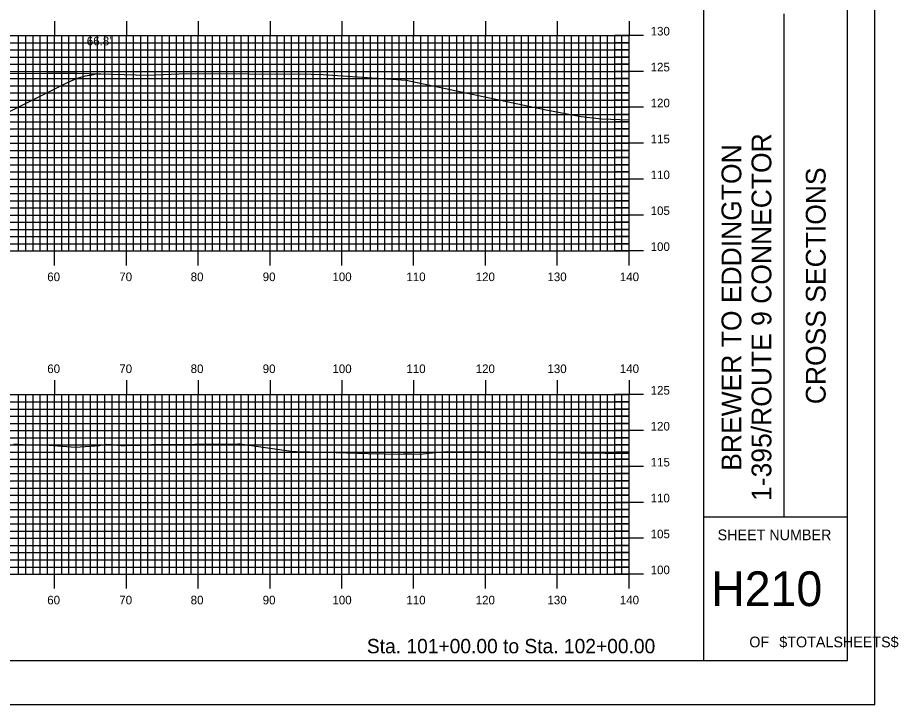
# Model space of a CAD drawing. Extents: x 1766907 to 1767250, y 442591 to 442811.
# Drawn here: x 1767127.3 to 1767249.9, y 442590.5 to 442686.2 of the extents above; entities that cross this region are included whole.
import ezdxf

# ---------------------------------------------------------------- set-up
doc = ezdxf.new("R2010")
doc.units = 0
for name, color, linetype in [('BORDER', 7, 'Continuous'), ('D_Roadway_Centerline', 7, 'Continuous'), ('D_Roadway_SlopeLines', 7, 'Continuous'), ('D_Text_Standard', 7, 'Continuous'), ('H_V ANNOTATION', 7, 'Continuous'), ('MAJOR', 7, 'Continuous'), ('MINOR', 7, 'Continuous'), ('PLOT BOUNDARY', 7, 'Continuous'), ('S_Roadway_Centerline', 7, 'Continuous')]:
    doc.layers.add(name, color=color, linetype=linetype)

msp = doc.modelspace()

# ---------------------------------------------------------------- linework, layer by layer
at = {"layer": 'BORDER'}
for p, q in [((1767222.82, 442596.67), (1767222.82, 442806.67)), ((1767234.01, 442616.67), (1767234.01, 442686.67)), ((1767222.82, 442616.67), (1767242.82, 442616.67))]:
    msp.add_line(p, q, dxfattribs=at)
msp.add_lwpolyline([(1766922.82, 442596.67), (1767242.82, 442596.67), (1767242.82, 442806.67), (1766922.82, 442806.67)], close=True, dxfattribs=at)
at = {"layer": 'D_Roadway_Centerline'}
msp.add_lwpolyline([(1767106.6, 442663.33), (1767134.22, 442677.14), (1767134.22, 442677.14), (1767135.34, 442677.63), (1767135.48, 442677.68), (1767135.6, 442677.72), (1767136.72, 442678.06), (1767137.89, 442678.26), (1767137.98, 442678.27), (1767138.05, 442678.28), (1767139.22, 442678.32)], dxfattribs=at)
at = {"layer": 'D_Roadway_SlopeLines'}
msp.add_lwpolyline([(1767106.6, 442663.33), (1767134.22, 442677.14), (1767135.48, 442677.68), (1767136.72, 442678.06), (1767137.98, 442678.27), (1767139.22, 442678.32)], dxfattribs=at)
at = {"layer": 'MAJOR'}
for p, q in [((1767132.42, 442685.67), (1767132.42, 442683.67)), ((1767142.42, 442685.67), (1767142.42, 442683.67)), ((1767152.42, 442685.67), (1767152.42, 442683.67)), ((1767162.42, 442685.67), (1767162.42, 442683.67)), ((1767172.42, 442685.67), (1767172.42, 442683.67)), ((1767182.42, 442685.67), (1767182.42, 442683.67)), ((1767192.42, 442685.67), (1767192.42, 442683.67)), ((1767202.42, 442685.67), (1767202.42, 442683.67)), ((1767212.42, 442685.67), (1767212.42, 442683.67)), ((1766932.42, 442683.67), (1767212.42, 442683.67)), ((1766932.42, 442683.67), (1767212.42, 442683.67)), ((1767132.42, 442653.67), (1767132.42, 442683.67)), ((1767142.42, 442653.67), (1767142.42, 442683.67)), ((1767152.42, 442653.67), (1767152.42, 442683.67)), ((1767162.42, 442653.67), (1767162.42, 442683.67)), ((1767172.42, 442653.67), (1767172.42, 442683.67)), ((1767182.42, 442653.67), (1767182.42, 442683.67)), ((1767192.42, 442653.67), (1767192.42, 442683.67)), ((1767202.42, 442653.67), (1767202.42, 442683.67)), ((1767214.43, 442683.67), (1767210.42, 442683.67)), ((1767212.42, 442653.67), (1767212.42, 442683.67)), ((1767212.42, 442653.67), (1767212.42, 442683.67)), ((1766932.42, 442678.67), (1767212.42, 442678.67)), ((1767214.43, 442678.67), (1767210.42, 442678.67)), ((1766932.42, 442673.67), (1767212.42, 442673.67)), ((1767214.43, 442673.67), (1767210.42, 442673.67)), ((1766932.42, 442668.67), (1767212.42, 442668.67)), ((1767214.43, 442668.67), (1767210.42, 442668.67)), ((1766932.42, 442663.67), (1767212.42, 442663.67)), ((1767214.43, 442663.67), (1767210.42, 442663.67)), ((1766932.42, 442658.67), (1767212.42, 442658.67)), ((1767214.43, 442658.67), (1767210.42, 442658.67)), ((1766932.42, 442653.67), (1767212.42, 442653.67)), ((1766932.42, 442653.67), (1767212.42, 442653.67)), ((1767132.42, 442651.66), (1767132.42, 442653.67)), ((1767142.42, 442651.66), (1767142.42, 442653.67)), ((1767152.42, 442651.66), (1767152.42, 442653.67)), ((1767162.42, 442651.66), (1767162.42, 442653.67)), ((1767172.42, 442651.66), (1767172.42, 442653.67)), ((1767182.42, 442651.66), (1767182.42, 442653.67)), ((1767192.42, 442651.66), (1767192.42, 442653.67)), ((1767202.42, 442651.66), (1767202.42, 442653.67)), ((1767214.43, 442653.67), (1767210.42, 442653.67)), ((1767212.42, 442651.66), (1767212.42, 442653.67)), ((1767132.42, 442635.67), (1767132.42, 442633.67)), ((1767142.42, 442635.67), (1767142.42, 442633.67)), ((1767152.42, 442635.67), (1767152.42, 442633.67)), ((1767162.42, 442635.67), (1767162.42, 442633.67)), ((1767172.42, 442635.67), (1767172.42, 442633.67)), ((1767182.42, 442635.67), (1767182.42, 442633.67)), ((1767192.42, 442635.67), (1767192.42, 442633.67)), ((1767202.42, 442635.67), (1767202.42, 442633.67)), ((1767212.42, 442635.67), (1767212.42, 442633.67)), ((1766932.42, 442633.67), (1767212.42, 442633.67)), ((1766932.42, 442633.67), (1767212.42, 442633.67)), ((1767132.42, 442608.67), (1767132.42, 442633.67)), ((1767142.42, 442608.67), (1767142.42, 442633.67)), ((1767152.42, 442608.67), (1767152.42, 442633.67)), ((1767162.42, 442608.67), (1767162.42, 442633.67)), ((1767172.42, 442608.67), (1767172.42, 442633.67)), ((1767182.42, 442608.67), (1767182.42, 442633.67)), ((1767192.42, 442608.67), (1767192.42, 442633.67)), ((1767202.42, 442608.67), (1767202.42, 442633.67)), ((1767214.43, 442633.67), (1767210.42, 442633.67)), ((1767212.42, 442608.67), (1767212.42, 442633.67)), ((1767212.42, 442608.67), (1767212.42, 442633.67)), ((1766932.42, 442628.67), (1767212.42, 442628.67)), ((1767214.43, 442628.67), (1767210.42, 442628.67)), ((1766932.42, 442623.67), (1767212.42, 442623.67)), ((1767214.43, 442623.67), (1767210.42, 442623.67)), ((1766932.42, 442618.67), (1767212.42, 442618.67)), ((1767214.43, 442618.67), (1767210.42, 442618.67)), ((1766932.42, 442613.67), (1767212.42, 442613.67)), ((1767214.43, 442613.67), (1767210.42, 442613.67)), ((1766932.42, 442608.67), (1767212.42, 442608.67)), ((1766932.42, 442608.67), (1767212.42, 442608.67)), ((1767132.42, 442606.66), (1767132.42, 442608.67)), ((1767142.42, 442606.66), (1767142.42, 442608.67)), ((1767152.42, 442606.66), (1767152.42, 442608.67)), ((1767162.42, 442606.66), (1767162.42, 442608.67)), ((1767172.42, 442606.66), (1767172.42, 442608.67)), ((1767182.42, 442606.66), (1767182.42, 442608.67)), ((1767192.42, 442606.66), (1767192.42, 442608.67)), ((1767202.42, 442606.66), (1767202.42, 442608.67)), ((1767214.43, 442608.67), (1767210.42, 442608.67)), ((1767212.42, 442606.66), (1767212.42, 442608.67))]:
    msp.add_line(p, q, dxfattribs=at)
at = {"layer": 'MINOR'}
for p, q in [((1767127.42, 442653.67), (1767127.42, 442683.67)), ((1767128.42, 442653.67), (1767128.42, 442683.67)), ((1767129.42, 442653.67), (1767129.42, 442683.67)), ((1767130.42, 442653.67), (1767130.42, 442683.67)), ((1767131.42, 442653.67), (1767131.42, 442683.67)), ((1767133.42, 442653.67), (1767133.42, 442683.67)), ((1767134.42, 442653.67), (1767134.42, 442683.67)), ((1767135.42, 442653.67), (1767135.42, 442683.67)), ((1767136.42, 442653.67), (1767136.42, 442683.67)), ((1767137.42, 442653.67), (1767137.42, 442683.67)), ((1767138.42, 442653.67), (1767138.42, 442683.67)), ((1767139.42, 442653.67), (1767139.42, 442683.67)), ((1767140.42, 442653.67), (1767140.42, 442683.67)), ((1767141.42, 442653.67), (1767141.42, 442683.67)), ((1767143.42, 442653.67), (1767143.42, 442683.67)), ((1767144.42, 442653.67), (1767144.42, 442683.67)), ((1767145.42, 442653.67), (1767145.42, 442683.67)), ((1767146.42, 442653.67), (1767146.42, 442683.67)), ((1767147.42, 442653.67), (1767147.42, 442683.67)), ((1767148.42, 442653.67), (1767148.42, 442683.67)), ((1767149.42, 442653.67), (1767149.42, 442683.67)), ((1767150.42, 442653.67), (1767150.42, 442683.67)), ((1767151.42, 442653.67), (1767151.42, 442683.67)), ((1767153.42, 442653.67), (1767153.42, 442683.67)), ((1767154.42, 442653.67), (1767154.42, 442683.67)), ((1767155.42, 442653.67), (1767155.42, 442683.67)), ((1767156.42, 442653.67), (1767156.42, 442683.67)), ((1767157.42, 442653.67), (1767157.42, 442683.67)), ((1767158.42, 442653.67), (1767158.42, 442683.67)), ((1767159.42, 442653.67), (1767159.42, 442683.67)), ((1767160.42, 442653.67), (1767160.42, 442683.67)), ((1767161.42, 442653.67), (1767161.42, 442683.67)), ((1767163.42, 442653.67), (1767163.42, 442683.67)), ((1767164.42, 442653.67), (1767164.42, 442683.67)), ((1767165.42, 442653.67), (1767165.42, 442683.67)), ((1767166.42, 442653.67), (1767166.42, 442683.67)), ((1767167.42, 442653.67), (1767167.42, 442683.67)), ((1767168.42, 442653.67), (1767168.42, 442683.67)), ((1767169.42, 442653.67), (1767169.42, 442683.67)), ((1767170.42, 442653.67), (1767170.42, 442683.67)), ((1767171.42, 442653.67), (1767171.42, 442683.67)), ((1767173.42, 442653.67), (1767173.42, 442683.67)), ((1767174.42, 442653.67), (1767174.42, 442683.67)), ((1767175.42, 442653.67), (1767175.42, 442683.67)), ((1767176.42, 442653.67), (1767176.42, 442683.67)), ((1767177.42, 442653.67), (1767177.42, 442683.67)), ((1767178.42, 442653.67), (1767178.42, 442683.67)), ((1767179.42, 442653.67), (1767179.42, 442683.67)), ((1767180.42, 442653.67), (1767180.42, 442683.67)), ((1767181.42, 442653.67), (1767181.42, 442683.67)), ((1767183.42, 442653.67), (1767183.42, 442683.67)), ((1767184.42, 442653.67), (1767184.42, 442683.67)), ((1767185.42, 442653.67), (1767185.42, 442683.67)), ((1767186.42, 442653.67), (1767186.42, 442683.67)), ((1767187.42, 442653.67), (1767187.42, 442683.67)), ((1767188.42, 442653.67), (1767188.42, 442683.67)), ((1767189.42, 442653.67), (1767189.42, 442683.67)), ((1767190.42, 442653.67), (1767190.42, 442683.67)), ((1767191.42, 442653.67), (1767191.42, 442683.67)), ((1767193.42, 442653.67), (1767193.42, 442683.67)), ((1767194.42, 442653.67), (1767194.42, 442683.67)), ((1767195.42, 442653.67), (1767195.42, 442683.67)), ((1767196.42, 442653.67), (1767196.42, 442683.67)), ((1767197.42, 442653.67), (1767197.42, 442683.67)), ((1767198.42, 442653.67), (1767198.42, 442683.67)), ((1767199.42, 442653.67), (1767199.42, 442683.67)), ((1767200.42, 442653.67), (1767200.42, 442683.67)), ((1767201.42, 442653.67), (1767201.42, 442683.67)), ((1767203.42, 442653.67), (1767203.42, 442683.67)), ((1767204.42, 442653.67), (1767204.42, 442683.67)), ((1767205.42, 442653.67), (1767205.42, 442683.67)), ((1767206.42, 442653.67), (1767206.42, 442683.67)), ((1767207.42, 442653.67), (1767207.42, 442683.67)), ((1767208.42, 442653.67), (1767208.42, 442683.67)), ((1767209.42, 442653.67), (1767209.42, 442683.67)), ((1767210.42, 442653.67), (1767210.42, 442683.67)), ((1767211.42, 442653.67), (1767211.42, 442683.67)), ((1766932.42, 442682.67), (1767212.42, 442682.67)), ((1766932.42, 442681.67), (1767212.42, 442681.67)), ((1767212.42, 442682.67), (1767210.42, 442682.67)), ((1767212.42, 442681.67), (1767210.42, 442681.67)), ((1766932.42, 442680.67), (1767212.42, 442680.67)), ((1767212.42, 442680.67), (1767210.42, 442680.67)), ((1766932.42, 442679.67), (1767212.42, 442679.67)), ((1767212.42, 442679.67), (1767210.42, 442679.67)), ((1766932.42, 442677.67), (1767212.42, 442677.67)), ((1766932.42, 442676.67), (1767212.42, 442676.67)), ((1767212.42, 442677.67), (1767210.42, 442677.67)), ((1767212.42, 442676.67), (1767210.42, 442676.67)), ((1766932.42, 442675.67), (1767212.42, 442675.67)), ((1767212.42, 442675.67), (1767210.42, 442675.67)), ((1766932.42, 442674.67), (1767212.42, 442674.67)), ((1767212.42, 442674.67), (1767210.42, 442674.67)), ((1766932.42, 442672.67), (1767212.42, 442672.67)), ((1767212.42, 442672.67), (1767210.42, 442672.67)), ((1766932.42, 442671.67), (1767212.42, 442671.67)), ((1766932.42, 442670.67), (1767212.42, 442670.67)), ((1767212.42, 442671.67), (1767210.42, 442671.67)), ((1767212.42, 442670.67), (1767210.42, 442670.67)), ((1766932.42, 442669.67), (1767212.42, 442669.67)), ((1767212.42, 442669.67), (1767210.42, 442669.67)), ((1766932.42, 442667.67), (1767212.42, 442667.67)), ((1767212.42, 442667.67), (1767210.42, 442667.67)), ((1766932.42, 442666.67), (1767212.42, 442666.67)), ((1766932.42, 442665.67), (1767212.42, 442665.67)), ((1767212.42, 442666.67), (1767210.42, 442666.67)), ((1767212.42, 442665.67), (1767210.42, 442665.67)), ((1766932.42, 442664.67), (1767212.42, 442664.67)), ((1767212.42, 442664.67), (1767210.42, 442664.67)), ((1766932.42, 442662.67), (1767212.42, 442662.67)), ((1767212.42, 442662.67), (1767210.42, 442662.67)), ((1766932.42, 442661.67), (1767212.42, 442661.67)), ((1767212.42, 442661.67), (1767210.42, 442661.67)), ((1766932.42, 442660.67), (1767212.42, 442660.67)), ((1766932.42, 442659.67), (1767212.42, 442659.67)), ((1767212.42, 442660.67), (1767210.42, 442660.67)), ((1767212.42, 442659.67), (1767210.42, 442659.67)), ((1766932.42, 442657.67), (1767212.42, 442657.67)), ((1767212.42, 442657.67), (1767210.42, 442657.67)), ((1766932.42, 442656.67), (1767212.42, 442656.67)), ((1767212.42, 442656.67), (1767210.42, 442656.67)), ((1766932.42, 442655.67), (1767212.42, 442655.67)), ((1766932.42, 442654.67), (1767212.42, 442654.67)), ((1767212.42, 442655.67), (1767210.42, 442655.67)), ((1767212.42, 442654.67), (1767210.42, 442654.67)), ((1766932.42, 442632.67), (1767212.42, 442632.67)), ((1767127.42, 442608.67), (1767127.42, 442633.67)), ((1767128.42, 442608.67), (1767128.42, 442633.67)), ((1767129.42, 442608.67), (1767129.42, 442633.67)), ((1767130.42, 442608.67), (1767130.42, 442633.67)), ((1767131.42, 442608.67), (1767131.42, 442633.67)), ((1767133.42, 442608.67), (1767133.42, 442633.67)), ((1767134.42, 442608.67), (1767134.42, 442633.67)), ((1767135.42, 442608.67), (1767135.42, 442633.67)), ((1767136.42, 442608.67), (1767136.42, 442633.67)), ((1767137.42, 442608.67), (1767137.42, 442633.67)), ((1767138.42, 442608.67), (1767138.42, 442633.67)), ((1767139.42, 442608.67), (1767139.42, 442633.67)), ((1767140.42, 442608.67), (1767140.42, 442633.67)), ((1767141.42, 442608.67), (1767141.42, 442633.67)), ((1767143.42, 442608.67), (1767143.42, 442633.67)), ((1767144.42, 442608.67), (1767144.42, 442633.67)), ((1767145.42, 442608.67), (1767145.42, 442633.67)), ((1767146.42, 442608.67), (1767146.42, 442633.67)), ((1767147.42, 442608.67), (1767147.42, 442633.67)), ((1767148.42, 442608.67), (1767148.42, 442633.67)), ((1767149.42, 442608.67), (1767149.42, 442633.67)), ((1767150.42, 442608.67), (1767150.42, 442633.67)), ((1767151.42, 442608.67), (1767151.42, 442633.67)), ((1767153.42, 442608.67), (1767153.42, 442633.67)), ((1767154.42, 442608.67), (1767154.42, 442633.67)), ((1767155.42, 442608.67), (1767155.42, 442633.67)), ((1767156.42, 442608.67), (1767156.42, 442633.67)), ((1767157.42, 442608.67), (1767157.42, 442633.67)), ((1767158.42, 442608.67), (1767158.42, 442633.67)), ((1767159.42, 442608.67), (1767159.42, 442633.67)), ((1767160.42, 442608.67), (1767160.42, 442633.67)), ((1767161.42, 442608.67), (1767161.42, 442633.67)), ((1767163.42, 442608.67), (1767163.42, 442633.67)), ((1767164.42, 442608.67), (1767164.42, 442633.67)), ((1767165.42, 442608.67), (1767165.42, 442633.67)), ((1767166.42, 442608.67), (1767166.42, 442633.67)), ((1767167.42, 442608.67), (1767167.42, 442633.67)), ((1767168.42, 442608.67), (1767168.42, 442633.67)), ((1767169.42, 442608.67), (1767169.42, 442633.67)), ((1767170.42, 442608.67), (1767170.42, 442633.67)), ((1767171.42, 442608.67), (1767171.42, 442633.67)), ((1767173.42, 442608.67), (1767173.42, 442633.67)), ((1767174.42, 442608.67), (1767174.42, 442633.67)), ((1767175.42, 442608.67), (1767175.42, 442633.67)), ((1767176.42, 442608.67), (1767176.42, 442633.67)), ((1767177.42, 442608.67), (1767177.42, 442633.67)), ((1767178.42, 442608.67), (1767178.42, 442633.67)), ((1767179.42, 442608.67), (1767179.42, 442633.67)), ((1767180.42, 442608.67), (1767180.42, 442633.67)), ((1767181.42, 442608.67), (1767181.42, 442633.67)), ((1767183.42, 442608.67), (1767183.42, 442633.67)), ((1767184.42, 442608.67), (1767184.42, 442633.67)), ((1767185.42, 442608.67), (1767185.42, 442633.67)), ((1767186.42, 442608.67), (1767186.42, 442633.67)), ((1767187.42, 442608.67), (1767187.42, 442633.67)), ((1767188.42, 442608.67), (1767188.42, 442633.67)), ((1767189.42, 442608.67), (1767189.42, 442633.67)), ((1767190.42, 442608.67), (1767190.42, 442633.67)), ((1767191.42, 442608.67), (1767191.42, 442633.67)), ((1767193.42, 442608.67), (1767193.42, 442633.67)), ((1767194.42, 442608.67), (1767194.42, 442633.67)), ((1767195.42, 442608.67), (1767195.42, 442633.67)), ((1767196.42, 442608.67), (1767196.42, 442633.67)), ((1767197.42, 442608.67), (1767197.42, 442633.67)), ((1767198.42, 442608.67), (1767198.42, 442633.67)), ((1767199.42, 442608.67), (1767199.42, 442633.67)), ((1767200.42, 442608.67), (1767200.42, 442633.67)), ((1767201.42, 442608.67), (1767201.42, 442633.67)), ((1767203.42, 442608.67), (1767203.42, 442633.67)), ((1767204.42, 442608.67), (1767204.42, 442633.67)), ((1767205.42, 442608.67), (1767205.42, 442633.67)), ((1767206.42, 442608.67), (1767206.42, 442633.67)), ((1767207.42, 442608.67), (1767207.42, 442633.67)), ((1767208.42, 442608.67), (1767208.42, 442633.67)), ((1767209.42, 442608.67), (1767209.42, 442633.67)), ((1767210.42, 442608.67), (1767210.42, 442633.67)), ((1767212.42, 442632.67), (1767210.42, 442632.67)), ((1767211.42, 442608.67), (1767211.42, 442633.67)), ((1766932.42, 442631.67), (1767212.42, 442631.67)), ((1767212.42, 442631.67), (1767210.42, 442631.67)), ((1766932.42, 442630.67), (1767212.42, 442630.67)), ((1767212.42, 442630.67), (1767210.42, 442630.67)), ((1766932.42, 442629.67), (1767212.42, 442629.67)), ((1767212.42, 442629.67), (1767210.42, 442629.67)), ((1766932.42, 442627.67), (1767212.42, 442627.67)), ((1767212.42, 442627.67), (1767210.42, 442627.67)), ((1766932.42, 442626.67), (1767212.42, 442626.67)), ((1767212.42, 442626.67), (1767210.42, 442626.67)), ((1766932.42, 442625.67), (1767212.42, 442625.67)), ((1767212.42, 442625.67), (1767210.42, 442625.67)), ((1766932.42, 442624.67), (1767212.42, 442624.67)), ((1767212.42, 442624.67), (1767210.42, 442624.67)), ((1766932.42, 442622.67), (1767212.42, 442622.67)), ((1766932.42, 442621.67), (1767212.42, 442621.67)), ((1767212.42, 442622.67), (1767210.42, 442622.67)), ((1767212.42, 442621.67), (1767210.42, 442621.67)), ((1766932.42, 442620.67), (1767212.42, 442620.67)), ((1767212.42, 442620.67), (1767210.42, 442620.67)), ((1766932.42, 442619.67), (1767212.42, 442619.67)), ((1767212.42, 442619.67), (1767210.42, 442619.67)), ((1766932.42, 442617.67), (1767212.42, 442617.67)), ((1766932.42, 442616.67), (1767212.42, 442616.67)), ((1767212.42, 442617.67), (1767210.42, 442617.67)), ((1767212.42, 442616.67), (1767210.42, 442616.67)), ((1766932.42, 442615.67), (1767212.42, 442615.67)), ((1767212.42, 442615.67), (1767210.42, 442615.67)), ((1766932.42, 442614.67), (1767212.42, 442614.67)), ((1767212.42, 442614.67), (1767210.42, 442614.67)), ((1766932.42, 442612.67), (1767212.42, 442612.67)), ((1766932.42, 442611.67), (1767212.42, 442611.67)), ((1767212.42, 442612.67), (1767210.42, 442612.67)), ((1767212.42, 442611.67), (1767210.42, 442611.67)), ((1766932.42, 442610.67), (1767212.42, 442610.67)), ((1767212.42, 442610.67), (1767210.42, 442610.67)), ((1766932.42, 442609.67), (1767212.42, 442609.67)), ((1767212.42, 442609.67), (1767210.42, 442609.67))]:
    msp.add_line(p, q, dxfattribs=at)
at = {"layer": 'PLOT BOUNDARY'}
msp.add_lwpolyline([(1766906.64, 442590.55), (1767246.64, 442590.55), (1767246.64, 442810.55), (1766906.64, 442810.55)], close=True, dxfattribs=at)
at = {"layer": 'S_Roadway_Centerline'}
for points in [[(1767124.53, 442678.38), (1767131.45, 442678.41), (1767135.59, 442678.43), (1767145.42, 442678.13), (1767150.78, 442678.38), (1767168.14, 442678.27), (1767169.82, 442678.25), (1767181.36, 442677.47), (1767200.63, 442673.36), (1767205.73, 442672.38), (1767208.58, 442672.06), (1767212.42, 442671.92)], [(1767126.76, 442626.82), (1767129.37, 442626.65), (1767131.07, 442626.7), (1767135.34, 442626.34), (1767138.66, 442626.6), (1767138.84, 442626.63), (1767139.67, 442626.77), (1767140.45, 442626.71), (1767140.57, 442626.7), (1767141.71, 442626.58), (1767142.19, 442626.6), (1767142.73, 442626.63), (1767143.92, 442626.61), (1767145.93, 442626.71), (1767157.94, 442626.83), (1767158.24, 442626.81), (1767165.7, 442625.77), (1767166.09, 442625.75), (1767171.65, 442625.62), (1767176.09, 442625.47), (1767180.7, 442625.37), (1767180.96, 442625.42), (1767181.27, 442625.44), (1767182.12, 442625.43), (1767183.39, 442625.4), (1767184.52, 442625.5), (1767187.07, 442625.74), (1767199.03, 442625.67), (1767212.42, 442625.46)]]:
    msp.add_lwpolyline(points, dxfattribs=at)

# ---------------------------------------------------------------- texts
at = {"layer": 'BORDER'}
for s, p in [('1-395/ROUTE 9 CONNECTOR', (1767232.23, 442618.87)), ('BREWER TO EDDINGTON', (1767228.05, 442623.07)), ('CROSS SECTIONS', (1767239.79, 442632.34))]:
    msp.add_text(s, height=2.7557, rotation=90, dxfattribs=at).set_placement(p)
for s, height, p in [('SHEET NUMBER', 1.4905, (1767224.75, 442613.4)), ('H210', 4.839, (1767223.85, 442604.23)), ('OF', 1.491, (1767229.16, 442598.49)), ('$TOTALSHEETS$', 1.4905, (1767233.34, 442598.49))]:
    msp.add_text(s, height=height, dxfattribs=at).set_placement(p)
at = {"layer": 'D_Text_Standard'}
msp.add_text("66.8'", height=1.2, dxfattribs=at).set_placement((1767136.91, 442682.3))
at = {"layer": 'H_V ANNOTATION'}
for s, height, p in [('130', 1.2, (1767215.42, 442683.67)), ('125', 1.2, (1767215.42, 442678.67)), ('120', 1.2, (1767215.42, 442673.67)), ('115', 1.2, (1767215.42, 442668.67)), ('110', 1.2, (1767215.42, 442663.67)), ('105', 1.2, (1767215.42, 442658.67)), ('100', 1.2, (1767215.42, 442653.67)), ('60', 1.2, (1767131.4, 442649.47)), ('70', 1.2, (1767141.43, 442649.47)), ('80', 1.2, (1767151.37, 442649.47)), ('90', 1.2, (1767161.4, 442649.47)), ('100', 1.2, (1767171.11, 442649.47)), ('110', 1.2, (1767181.41, 442649.47)), ('120', 1.2, (1767191.06, 442649.47)), ('130', 1.2, (1767201.05, 442649.47)), ('140', 1.2, (1767211.13, 442649.47)), ('60', 1.2, (1767131.4, 442636.67)), ('70', 1.2, (1767141.43, 442636.67)), ('80', 1.2, (1767151.37, 442636.67)), ('90', 1.2, (1767161.4, 442636.67)), ('100', 1.2, (1767171.11, 442636.67)), ('110', 1.2, (1767181.41, 442636.67)), ('120', 1.2, (1767191.06, 442636.67)), ('130', 1.2, (1767201.05, 442636.67)), ('140', 1.2, (1767211.13, 442636.67)), ('125', 1.2, (1767215.42, 442633.67)), ('120', 1.2, (1767215.42, 442628.67)), ('115', 1.2, (1767215.42, 442623.67)), ('110', 1.2, (1767215.42, 442618.67)), ('105', 1.2, (1767215.42, 442613.67)), ('100', 1.2, (1767215.42, 442608.67)), ('60', 1.2, (1767131.4, 442604.47)), ('70', 1.2, (1767141.43, 442604.47)), ('80', 1.2, (1767151.37, 442604.47)), ('90', 1.2, (1767161.4, 442604.47)), ('100', 1.2, (1767171.11, 442604.47)), ('110', 1.2, (1767181.41, 442604.47)), ('120', 1.2, (1767191.06, 442604.47)), ('130', 1.2, (1767201.05, 442604.47)), ('140', 1.2, (1767211.13, 442604.47)), ('Sta. 101+00.00 to Sta. 102+00.00', 2.0004, (1767175.91, 442597.66))]:
    msp.add_text(s, height=height, dxfattribs=at).set_placement(p)

doc.saveas('drawing.dxf')
